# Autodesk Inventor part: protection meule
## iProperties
Shininess: 64.0
Length Units: 11269
Angle Units: 11279
Time Units: 11290
Mass Units: 11283
Length Display Precision: 3
Angle Display Precision: 2
Compacted: True
Part Number: protection meule
Document SubType Name: Modeling
Created: 2005-01
Material: Par défaut
Designer: LEGERET Philippe
Density: 0.0
Volumn: 0.0
Area: 0.0
PropertySet Name: Model Information
Control State: 0
Master: False
Checked Out: False
Author: LEGERET Philippe
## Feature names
1. Extrusion1
2. Extrusion2
3. Chanfrein1 [Chamfer]
